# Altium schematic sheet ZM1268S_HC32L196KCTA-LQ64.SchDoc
size A3; DocumentNumber: 3; PageSetup: Record=PageOptions|CenterHorizontal=True|CenterVertical=True|PrintScale=1.00|XCorrection=1.00|YCorrection=1.00|PrintKind=0|BorderSize=5000000|LeftOffset=0|BottomOffset=0|Orientation=2|PaperLength=1000|PaperWidth=1000|Scale=100|PaperSource=7|PrintQuality=600|MediaType=1|DitherType=10|PaperKind=A4|PrintScaleMode=1
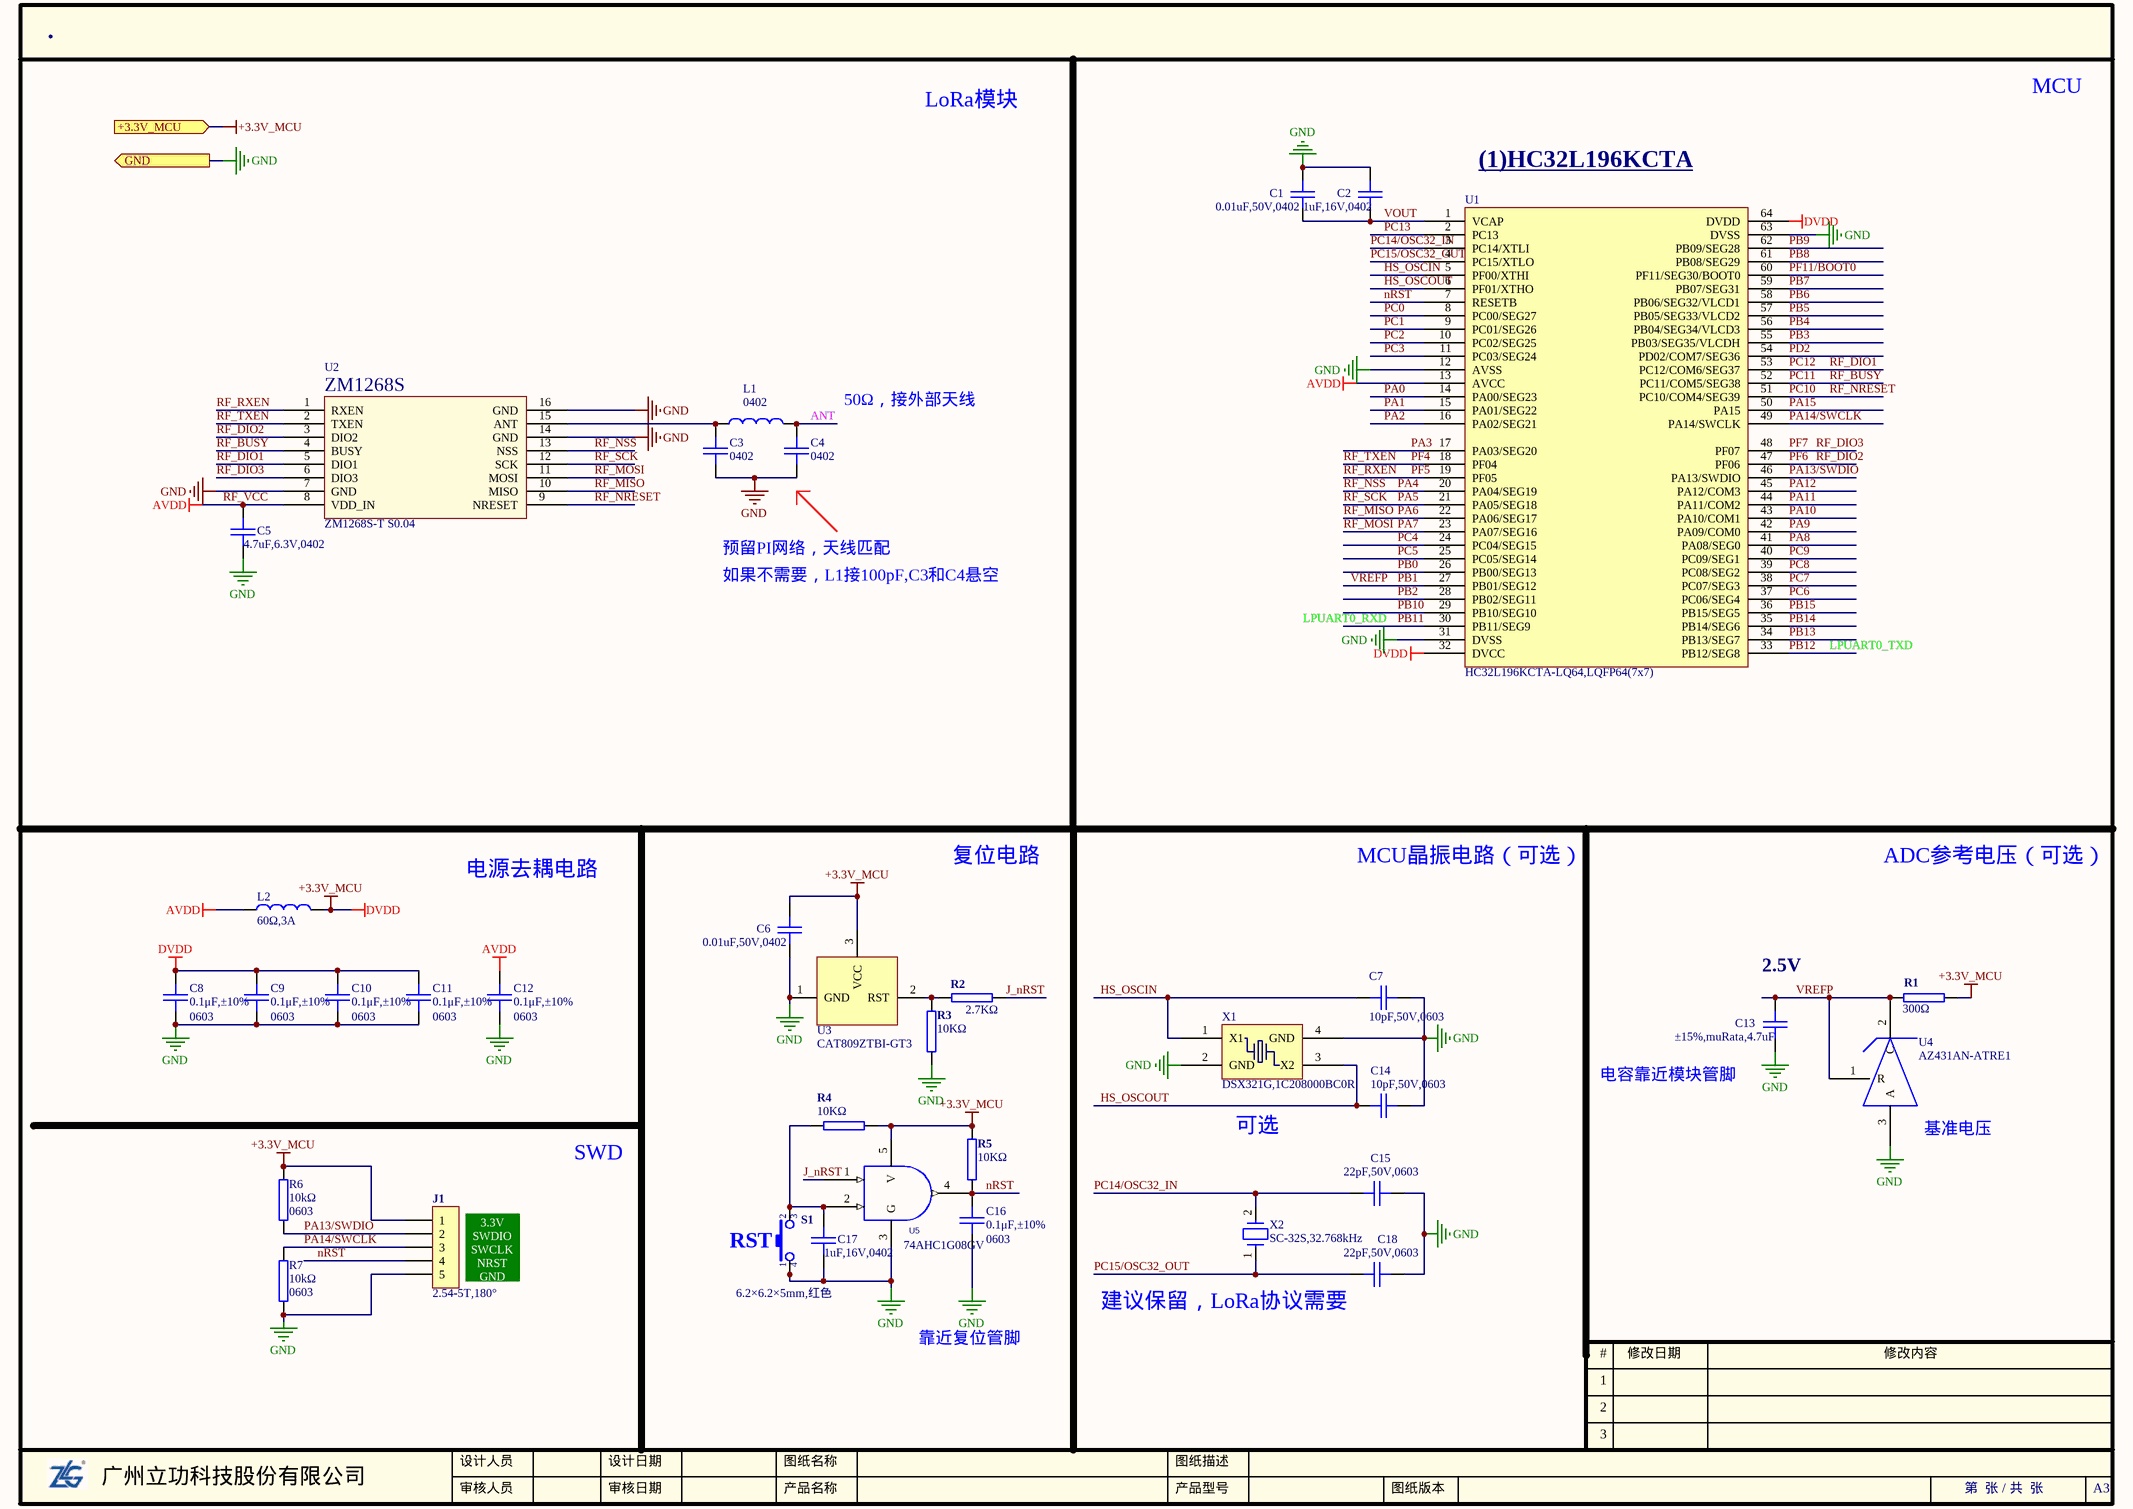
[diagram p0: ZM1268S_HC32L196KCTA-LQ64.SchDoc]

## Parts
C1  0.01uF,50V,0402  [0402C]
C2  1uF,16V,0402  [0402C]
C3  封装: 0402  [0402C]  (hidden comment: 4.7uF,6.3V,0402)
C4  封装: 0402  [0402C]  (hidden comment: 4.7uF,6.3V,0402)
C5  4.7uF,6.3V,0402  [0402C]
C6  0.01uF,50V,0402  [0402C]
C7  10pF,50V,0603  [0603C]
C8  封装: 0603  [0201C]  (hidden comment: 0.1μF,±10%)
C9  封装: 0603  [0201C]  (hidden comment: 0.1μF,±10%)
C10  封装: 0603  [0201C]  (hidden comment: 0.1μF,±10%)
C11  封装: 0603  [0201C]  (hidden comment: 0.1μF,±10%)
C12  封装: 0603  [0201C]  (hidden comment: 0.1μF,±10%)
C13  ±15%,muRata,4.7uF  [0603C]
C14  10pF,50V,0603  [0603C]
C15  22pF,50V,0603  [0603C]
C16  封装: 0603  [0201C]  (hidden comment: 0.1μF,±10%)
C17  1uF,16V,0402  [0402C]
C18  22pF,50V,0603  [0603C]
J1  2.54-5T,180°  [CON250P580W100D50S-5DIP]
L1  封装: 0402  [0402L]  (hidden comment: LQG15HS56NJ02D,56nH)
L2  60Ω,3A  [0805L]
R1  300Ω  [0603R]
R2  2.7KΩ  [0603R]
R3  10KΩ  [0603R]
R4  10KΩ  [0603R]
R5  10KΩ  [0603R]
R6  封装: 0603  [0603R]  (hidden comment: 10kΩ)
R7  封装: 0603  [0603R]  (hidden comment: 10kΩ)
S1  6.2×6.2×5mm,红色  [KEY-6S]
U1  HC32L196KCTA-LQ64,LQFP64(7x7)  [QFP40P900X900X160-64N]
U2  ZM1268S-T S0.04  [ZM1268S-T_REVB]
U3  CAT809ZTBI-GT3  [SOT-23]
U4  AZ431AN-ATRE1  [SOT-23]
U5  value 74AHC1G08GV  [SOT-23-5]  (hidden comment: 74AHC1G08)
X1  DSX321G,1C208000BC0R  [OSCCC250X320X100-4N]  (no BOM)
X2  SC-32S,32.768kHz  [XTAL320X150X90]  (no BOM)

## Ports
+3.3V_MCU (in), GND (out)

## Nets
+3.3V_MCU: C6.1 C8.1 C9.1 C10.1 C11.1 J1.1 L2.2 R1.2 R4.2 R5.2 R6.2 U1.32(DVCC) U1.64(DVDD) U3.3(VCC) U5.5(V) ; port +3.3V_MCU  [also labelled DVDD]
GND: C1.1 C2.1 C3.2 C4.2 C5.2 C6.2 C7.2 C8.2 C9.2 C10.2 C11.2 C12.2 C13.2 C14.2 C15.2 C16.2 C17.2 C18.2 J1.5 R3.1 R7.1 S1.1 S1.4 U1.12(AVSS) U1.31(DVSS) U1.63(DVSS) U2.7(GND) U2.14(GND) U2.16(GND) U3.1(GND) U4.3(A) U5.3(G) X1.2(GND) X1.4(GND) ; port GND
RF_VCC: C5.1 C12.1 L2.1 U1.13(AVCC) U2.8(VDD_IN)  [also labelled AVDD]
ANT: C4.1 L1.2
HS_OSCIN: C7.1 U1.5(PF00/XTHI) X1.1(X1)
HS_OSCOUT: C14.1 U1.6(PF01/XTHO) X1.3(X2)
J_nRST: R2.2 U5.1(IN_B)
nRST: C16.1 J1.4 R5.1 U1.7(RESETB) U5.4(OUT_Y)
PA0: U1.14(PA00/SEG23)
PA1: U1.15(PA01/SEG22)
PA2: U1.16(PA02/SEG21)
PA3: U1.17(PA03/SEG20)
PA4: U1.20(PA04/SEG19) U2.13(NSS)  [also labelled RF_NSS]
PA5: U1.21(PA05/SEG18) U2.12(SCK)  [also labelled RF_SCK]
PA6: U1.22(PA06/SEG17) U2.10(MISO)  [also labelled RF_MISO]
PA7: U1.23(PA07/SEG16) U2.11(MOSI)  [also labelled RF_MOSI]
PA8: U1.41(PA08/SEG0)
PA9: U1.42(PA09/COM0)
PA10: U1.43(PA10/COM1)
PA11: U1.44(PA11/COM2)
PA12: U1.45(PA12/COM3)
PA13/SWDIO: J1.2 R6.1 U1.46(PA13/SWDIO)
PA14/SWCLK: J1.3 R7.2 U1.49(PA14/SWCLK)
PA15: U1.50(PA15)
PB0: U1.26(PB00/SEG13)
PB1: C13.1 R1.1 U1.27(PB01/SEG12) U4.1(R) U4.2(C)  [also labelled VREFP]
PB2: U1.28(PB02/SEG11)
PB3: U1.55(PB03/SEG35/VLCDH)
PB4: U1.56(PB04/SEG34/VLCD3)
PB5: U1.57(PB05/SEG33/VLCD2)
PB6: U1.58(PB06/SEG32/VLCD1)
PB7: U1.59(PB07/SEG31)
PB8: U1.61(PB08/SEG29)
PB9: U1.62(PB09/SEG28)
PB10: U1.29(PB10/SEG10)
PB11: U1.30(PB11/SEG9)
PB12: U1.33(PB12/SEG8)
PB13: U1.34(PB13/SEG7)
PB14: U1.35(PB14/SEG6)
PB15: U1.36(PB15/SEG5)
PC0: U1.8(PC00/SEG27)
PC1: U1.9(PC01/SEG26)
PC2: U1.10(PC02/SEG25)
PC3: U1.11(PC03/SEG24)
PC4: U1.24(PC04/SEG15)
PC5: U1.25(PC05/SEG14)
PC6: U1.37(PC06/SEG4)
PC7: U1.38(PC07/SEG3)
PC8: U1.39(PC08/SEG2)
PC9: U1.40(PC09/SEG1)
PC10: U1.51(PC10/COM4/SEG39) U2.9(NRESET)  [also labelled RF_NRESET]
PC11: U1.52(PC11/COM5/SEG38) U2.4(BUSY)  [also labelled RF_BUSY]
PC12: U1.53(PC12/COM6/SEG37) U2.5(DIO1)  [also labelled RF_DIO1]
PC13: U1.2(PC13)
PC14/OSC32_IN: C15.1 U1.3(PC14/XTLI) X2.2
PC15/OSC32_OUT: C18.1 U1.4(PC15/XTLO) X2.1
PD2: U1.54(PD02/COM7/SEG36)
PF4: U1.18(PF04) U2.2(TXEN)  [also labelled RF_TXEN]
PF5: U1.19(PF05) U2.1(RXEN)  [also labelled RF_RXEN]
PF6: U1.47(PF06) U2.3(DIO2)  [also labelled RF_DIO2]
PF7: U1.48(PF07) U2.6(DIO3)  [also labelled RF_DIO3]
PF11/BOOT0: U1.60(PF11/SEG30/BOOT0)
VOUT: C1.2 C2.2 U1.1(VCAP)
NetC3_1: C3.1 L1.1 U2.15(ANT)
NetC17_1: C17.1 R4.1 S1.2 S1.3 U5.2(IN_A)
NetR2_1: R2.1 R3.2 U3.2(RST)

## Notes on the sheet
- LoRa模块
- MCU
- (near U1) (1)HC32L196KCTA
- 50Ω，接外部天线
- 预留PI网络，天线匹配
- 如果不需要，L1接100pF,C3和C4悬空
- LPUART0_RXD
- LPUART0_TXD
- 电源去耦电路
- 复位电路
- MCU晶振电路（可选）
- ADC参考电压（可选）
- (near C13) 2.5V
- 电容靠近模块管脚
- SWD
- (near X1) 可选
- (near U4) 基准电压
- (near J1) 3.3V
  SWDIO
  SWCLK
  NRST
  GND
- (near X2) 建议保留，LoRa协议需要
- 靠近复位管脚
- Labels drawn without touching a wire or pin: RST

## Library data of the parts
C1 C6 = 02.01.00275: GRM155R71H103KA88D,0402,MURATA,0.01uF,X7R,±10%,50V,; 旧物料代码: 1.02.17.0019; 名称: 电容; 封装: 0402; 贴片和直插: SMT; 器件优选方案: 通用物料
C2 C17 = 02.01.00333: GRM155R61C105KA12D,0402,MURATA,1uF,X5R,±10%,16V,; 旧物料代码: 1.02.17.0092; 名称: 电容; 封装: 0402; 贴片和直插: SMT; PCB备注: 无数据手册，依据采购部提供的信息添加的封装。; 器件优选方案: 通用物料
C3 C4 = 02.01.00315: GRM155R60J475ME87D,0402,MURATA,4.7uF,X5R,±20%,6.3V,; 旧物料代码: 1.02.17.0073; 名称: 电容; 贴片和直插: SMT; 器件优选方案: 推荐使用
C5 = 02.01.00315: GRM155R60J475ME87D,0402,MURATA,4.7uF,X5R,±20%,6.3V,; 旧物料代码: 1.02.17.0073; 名称: 电容; 封装: 0402; 贴片和直插: SMT; 器件优选方案: 推荐使用
C7 C14 = 02.01.00129: 10P,0603,MURATA,10pF,COG,±5%,50V,; 旧物料代码: 1.02.01.0031; 名称: 电容; 封装: 0603; 贴片和直插: SMT; 器件优选方案: 不推荐使用
C8-C12 C16 = 02.01.00416: GRM033R61A104KE15D,0201,muRata,0.1μF,X5R ±10%,10V; 名称: 陶瓷电容; 贴片和直插: SMT; 器件优选方案: 通用物料
C13 = 02.01.00449: GRM188R61C475KAAJD,4.7uF,16V,±15%,X5R,0603,muRata; 名称: 电容; 封装: 0603; 贴片和直插: SMT; PCB备注: 190510CZY; 器件优选方案: 通用物料
C15 C18 = 02.01.00009: GRM1885C1H220JA01D,0603,MURATA,22pF,COG,±5%,50V,; 旧物料代码: 1.02.01.0005; 名称: 电容; 封装: 0603; 贴片和直插: SMT; 器件优选方案: 不推荐使用
J1 = 1.10.06.0012: 2.54-5T,180°,,*; 名称: 插座; 贴片和直插: THT; PCB备注: xhm-lq-wyy-150123 / 150918mxz; 器件优选方案: 正常状态，可以选用
L1 = 03.01.00539: LQG15HS56NJ02D,56nH,250mA,±5%,0402,muRata; 名称: 电感; 贴片和直插: SMT; PCB备注: 190510CZY; 器件优选方案: 待导入物料
L2 = 1.03.03.0015: 60Ω,3A,DCR30mΩ,BH05Y354S-60R,SMD,0805,丰晶,RoHS; 名称: 磁珠; 封装: 0805; 贴片和直插: SMT; 器件优选方案: 正常状态，可以选用
R1 = 1.01.01.0030: 300Ω,0603,*,RoHS; 名称: 电阻; 封装: 0603; 设备封装名称: R0603_300R; 厂商: Ralec; 贴片和直插: SMT; 器件优选方案: 正常状态，可以选用
R2 = 1.01.01.0040: 2.7KΩ,0603,*,RoHS; 名称: 电阻; 封装: 0603; 设备封装名称: R0603_2.7K; 厂商: Ralec; 贴片和直插: SMT; 器件优选方案: 正常状态，可以选用
R3-R5 = 1.01.01.0051: 10KΩ,0603,*,RoHS; 名称: 电阻; 封装: 0603; 设备封装名称: R0603_10K; 厂商: Ralec; 贴片和直插: SMT; 器件优选方案: 正常状态，可以选用
R6 R7 = 1.01.01.0052: 10KΩ,±1%,0603,*,RoHS; 名称: 电阻; 设备封装名称: R0603_10K_1%; 厂商: Ralec; 贴片和直插: SMT
S1 = 1.09.01.0004: 6.2×6.2×5mm,红色,DTSM-62R-V-T/R,SMD; 名称: 轻触按键; 贴片和直插: SMT; 器件优选方案: 正常状态，可以选用
U1 = 08.01.04536: HC32L196KCTA-LQ64,LQFP64(7x7),HDSC,LQFP64,华大半导体; 名称: 集成电路; 封装: LQFP-64; 贴片和直插: SMT; PCB备注: 200515CZY; 器件优选方案: 待导入物料
U2 = 78.04.00105: 名称: LoRa模块; 厂商: ZHIYUAN; 贴片和直插: SMT; PCB备注: 200515CZY
U3 = 1.05.10.0708: CAT809ZTBI-GT3,SOT-23,ON,RoHS; 名称: 集成电路; 贴片和直插: SMT; PCB备注: 171109 YYF; 器件优选方案: 正常状态，可以选用
U4 = 1.05.09.0239: AZ431AN-ATRE1,Diodes,SOT-23,RoHS; 名称: 集成电路; 贴片和直插: SMT; PCB备注: 170516 hcj; 器件优选方案: 正常状态，可以选用
U5 = 1.05.05.0093: 74AHC1G08GV,SOT-753,NXP,RoHS; Manufacturer: PHILIPS; ID: 77; 名称: IC; 设备封装名称: SOT-753_74AHC1G08GV; 贴片和直插: SMT
X1 = 12.02.00214: DSX321G,1C208000BC0R,8.000MHZ,10ppm,12pF,SMT,KDS; 名称: 无源晶体振荡器; PCB备注: 190612 yyf; 器件优选方案: 待导入物料
X2 = 1.07.02.0056: SC-32S,32.768kHz,12.5pF,±20ppm,SMD3215,SII,RoHS; 名称: 晶振; 贴片和直插: SMT; PCB备注: 171129ZW; 器件优选方案: 正常状态，可以选用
